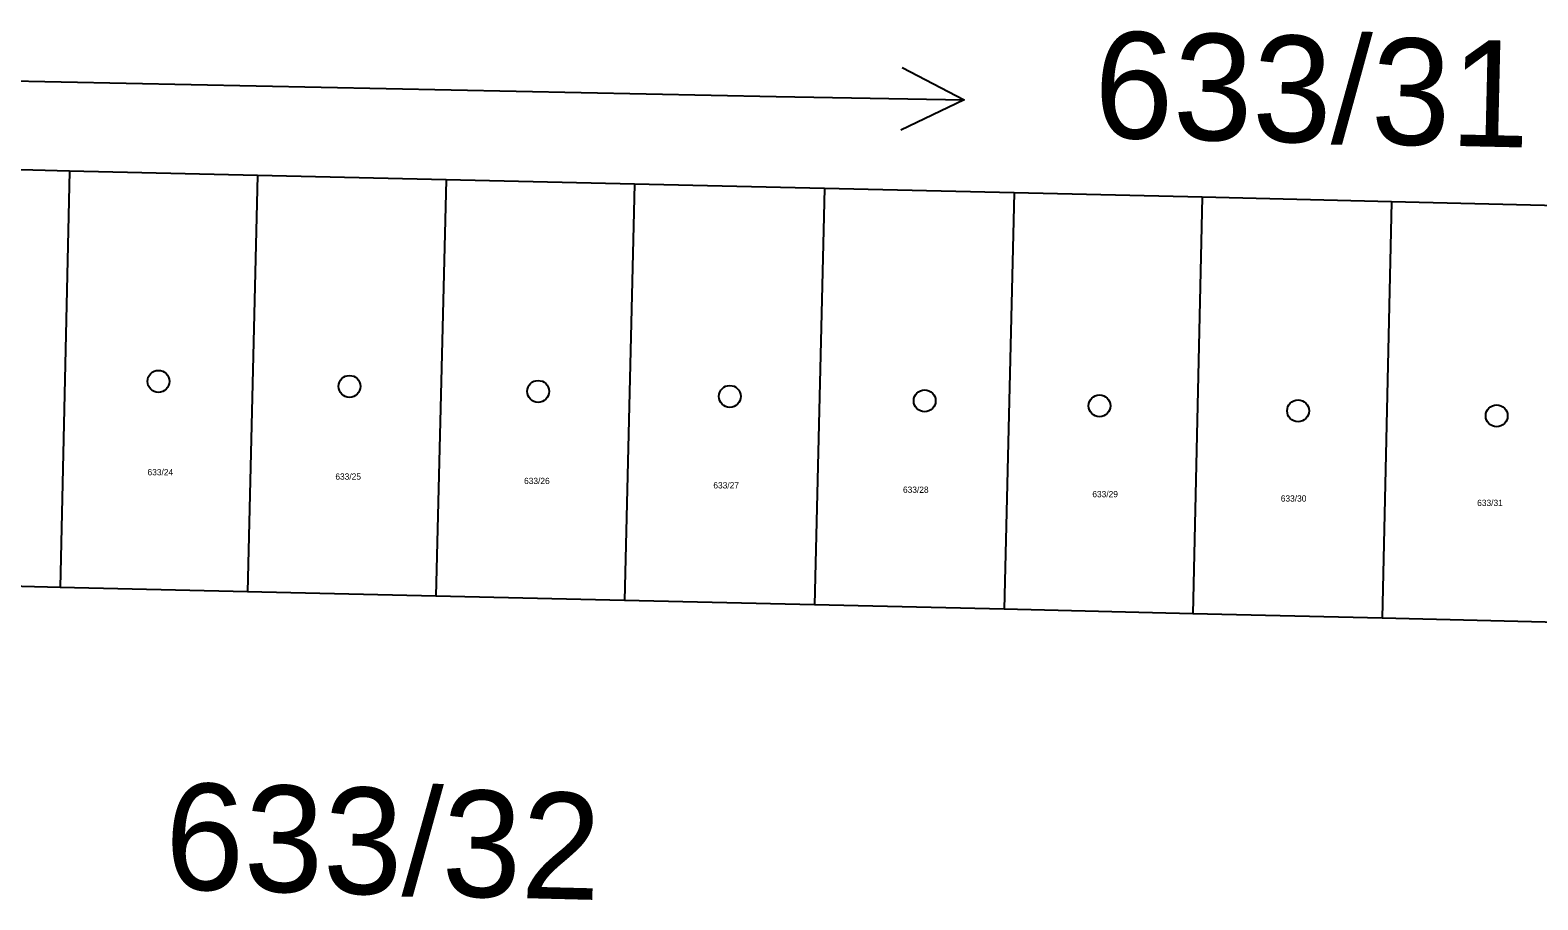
# Model space of a CAD drawing. Extents: x -822293 to -820259, y -1071573 to -1068794.
# Drawn here: x -820774 to -820749.93, y -1069520.06 to -1069506.17 of the extents above; entities that cross this region are included whole.
import ezdxf

# ---------------------------------------------------------------- set-up
doc = ezdxf.new("R2010")
doc.units = 0
for name, color, linetype in [('Vrstva 1', 7, 'Continuous'), ('Vrstva 16', 7, 'Continuous'), ('Vrstva 18', 7, 'Continuous'), ('Vrstva 19', 7, 'Continuous'), ('Vrstva 25', 7, 'Continuous')]:
    doc.layers.add(name, color=color, linetype=linetype)

msp = doc.modelspace()

# ---------------------------------------------------------------- linework, layer by layer
at = {"layer": 'Vrstva 1'}
for p, q in [((-820773.37, -1069508.42), (-820776.38, -1069508.35)), ((-820773.37, -1069508.42), (-820773.52, -1069515.07)), ((-820770.37, -1069508.49), (-820773.37, -1069508.42)), ((-820770.37, -1069508.49), (-820770.53, -1069515.14)), ((-820767.36, -1069508.56), (-820770.37, -1069508.49)), ((-820767.36, -1069508.56), (-820767.52, -1069515.21)), ((-820764.35, -1069508.63), (-820767.36, -1069508.56)), ((-820764.35, -1069508.63), (-820764.51, -1069515.28)), ((-820761.32, -1069508.7), (-820764.35, -1069508.63)), ((-820761.32, -1069508.7), (-820761.48, -1069515.35)), ((-820758.29, -1069508.77), (-820761.32, -1069508.7)), ((-820758.29, -1069508.77), (-820758.45, -1069515.42)), ((-820755.29, -1069508.84), (-820758.29, -1069508.77)), ((-820755.29, -1069508.84), (-820755.44, -1069515.49)), ((-820752.27, -1069508.91), (-820755.29, -1069508.84)), ((-820752.27, -1069508.91), (-820752.42, -1069515.56)), ((-820749.04, -1069508.99), (-820752.27, -1069508.91)), ((-820773.52, -1069515.07), (-820776.53, -1069515)), ((-820770.53, -1069515.14), (-820773.52, -1069515.07)), ((-820767.52, -1069515.21), (-820770.53, -1069515.14)), ((-820764.51, -1069515.28), (-820767.52, -1069515.21)), ((-820761.48, -1069515.35), (-820764.51, -1069515.28)), ((-820758.45, -1069515.42), (-820761.48, -1069515.35)), ((-820755.44, -1069515.49), (-820758.45, -1069515.42)), ((-820752.42, -1069515.56), (-820755.44, -1069515.49)), ((-820749.19, -1069515.64), (-820752.42, -1069515.56))]:
    msp.add_line(p, q, dxfattribs=at)
at = {"layer": 'Vrstva 16'}
for p, q in [((-820784.03, -1069506.78), (-820762.09, -1069507.23)), ((-820762.09, -1069507.23), (-820759.091, -1069507.285))]:
    msp.add_line(p, q, dxfattribs=at)
msp.add_lwpolyline([(-820760.081, -1069506.767), (-820759.091, -1069507.285), (-820760.1, -1069507.767)], dxfattribs=at)
at = {"layer": 'Vrstva 25'}
for centre in [(-820771.95, -1069511.78), (-820768.9, -1069511.86), (-820765.89, -1069511.94), (-820762.83, -1069512.02), (-820759.72, -1069512.09), (-820756.93, -1069512.17), (-820753.76, -1069512.25), (-820750.59, -1069512.33)]:
    msp.add_circle(centre, 0.175, dxfattribs=at)

# ---------------------------------------------------------------- texts
at = {"layer": 'Vrstva 16'}
msp.add_text('633/31', height=1.7, rotation=358.6716, dxfattribs=at).set_placement((-820757.03, -1069507.885))
at = {"layer": 'Vrstva 18'}
msp.add_text('633/32', height=1.7, rotation=358.548, dxfattribs=at).set_placement((-820771.862, -1069519.888))
at = {"layer": 'Vrstva 19'}
for s, p in [('633/24', (-820772.124, -1069513.28)), ('633/25', (-820769.126, -1069513.35)), ('633/26', (-820766.114, -1069513.42)), ('633/27', (-820763.093, -1069513.49)), ('633/28', (-820760.066, -1069513.56)), ('633/29', (-820757.044, -1069513.63)), ('633/30', (-820754.036, -1069513.7)), ('633/31', (-820750.901, -1069513.77))]:
    msp.add_text(s, height=0.1, dxfattribs=at).set_placement(p)

doc.saveas('drawing.dxf')
